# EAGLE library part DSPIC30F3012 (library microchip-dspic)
dsPIC Sensor DSP
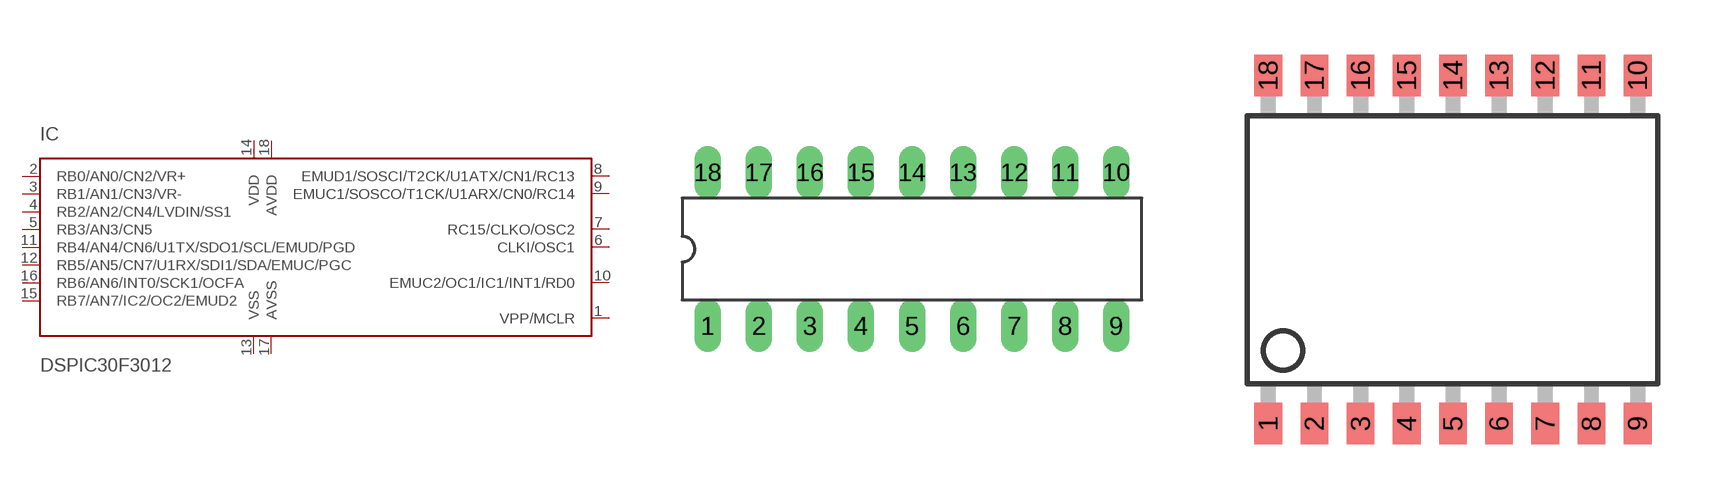
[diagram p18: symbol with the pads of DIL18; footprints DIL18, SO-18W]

Designator prefix IC

## DSPIC30F3012/P  [DIL18]
1  VPP/MCLR  in
2  RB0/AN0/CN2/VR+
3  RB1/AN1/CN3/VR-
4  RB2/AN2/CN4/LVDIN/SS1
5  RB3/AN3/CN5
6  CLKI/OSC1
7  RC15/CLKO/OSC2
8  EMUD1/SOSCI/T2CK/U1ATX/CN1/RC13
9  EMUC1/SOSCO/T1CK/U1ARX/CN0/RC14
10  EMUC2/OC1/IC1/INT1/RD0
11  RB4/AN4/CN6/U1TX/SDO1/SCL/EMUD/PGD
12  RB5/AN5/CN7/U1RX/SDI1/SDA/EMUC/PGC
13  VSS  pwr
14  VDD  pwr
15  RB7/AN7/IC2/OC2/EMUD2
16  RB6/AN6/INT0/SCK1/OCFA
17  AVSS  pwr
18  AVDD  pwr

## DSPIC30F3012/SO  [SO-18W]
Pads as for DIL18

## DSPIC30F3012/ML  [QFN44-8X8]
1  RB5/AN5/CN7/U1RX/SDI1/SDA/EMUC/PGC
4  VDD  pwr
12  RB7/AN7/IC2/OC2/EMUD2
14  RB6/AN6/INT0/SCK1/OCFA
16  AVSS  pwr
17  AVDD  pwr
18  VPP/MCLR  in
19  RB0/AN0/CN2/VR+
20  RB1/AN1/CN3/VR-
23  RB2/AN2/CN4/LVDIN/SS1
25  RB3/AN3/CN5
30  VSS  pwr
32  CLKI/OSC1
33  RC15/CLKO/OSC2
34  EMUD1/SOSCI/T2CK/U1ATX/CN1/RC13
35  EMUC1/SOSCO/T1CK/U1ARX/CN0/RC14
42  EMUC2/OC1/IC1/INT1/RD0
44  RB4/AN4/CN6/U1TX/SDO1/SCL/EMUD/PGD

## Footprint DIL18 (pad centres in mm)
Dual In Line package type P
drill 0.813 long: 1 -10.16,-3.81; 2 -7.62,-3.81; 3 -5.08,-3.81; 4 -2.54,-3.81; 5 0,-3.81; 6 2.54,-3.81; 7 5.08,-3.81; 8 7.62,-3.81; 9 10.16,-3.81; 10 10.16,3.81; 11 7.62,3.81; 12 5.08,3.81; 13 2.54,3.81; 14 0,3.81; 15 -2.54,3.81; 16 -5.08,3.81; 17 -7.62,3.81; 18 -10.16,3.81

## Footprint SO-18W (pad centres in mm)
Small Outline Wide Plastic Gull Wing 300-mil body, package type SO
smd 0.762 x 1.143: 1 -5.08,-4.788; 2 -3.81,-4.788; 3 -2.54,-4.788; 4 -1.27,-4.788; 5 0,-4.788; 6 1.27,-4.788; 7 2.54,-4.788; 8 3.81,-4.788; 9 5.08,-4.788; 10 5.08,4.788; 11 3.81,4.788; 12 2.54,4.788; 13 1.27,4.788; 14 0,4.788; 15 -1.27,4.788; 16 -2.54,4.788; 17 -3.81,4.788; 18 -5.08,4.788

## Footprint QFN44-8X8 (pad centres in mm)
Quad Flat No Lead
smd 0.6 x 0.37: 1 3.825,-3.25; 2 3.825,-2.6; 3 3.825,-1.95; 4 3.825,-1.3; 5 3.825,-0.65; 6 3.825,0; 7 3.825,0.65; 8 3.825,1.3; 9 3.825,1.95; 10 3.825,2.6; 11 3.825,3.25; 23 -3.825,3.25; 24 -3.825,2.6; 25 -3.825,1.95; 26 -3.825,1.3; 27 -3.825,0.65; 28 -3.825,0; 29 -3.825,-0.65; 30 -3.825,-1.3; 31 -3.825,-1.95; 32 -3.825,-2.6; 33 -3.825,-3.25
smd 0.37 x 0.6: 12 3.25,3.825; 13 2.6,3.825; 14 1.95,3.825; 15 1.3,3.825; 16 0.65,3.825; 17 0,3.825; 18 -0.65,3.825; 19 -1.3,3.825; 20 -1.95,3.825; 21 -2.6,3.825; 22 -3.25,3.825; 34 -3.25,-3.825; 35 -2.6,-3.825; 36 -1.95,-3.825; 37 -1.3,-3.825; 38 -0.65,-3.825; 39 0,-3.825; 40 0.65,-3.825; 41 1.3,-3.825; 42 1.95,-3.825; 43 2.6,-3.825; 44 3.25,-3.825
